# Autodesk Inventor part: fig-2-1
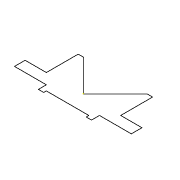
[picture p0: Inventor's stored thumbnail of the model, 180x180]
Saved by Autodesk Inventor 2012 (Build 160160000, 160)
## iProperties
Created: 2011-06
Part Number: fig-2-1
Material: Default
Document SubType Name: Modeling
Designer: CadCim
Density: 1 g/cm^3
Author: CadCim
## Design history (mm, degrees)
sketch "Sketch1"
  geometry: L1 (0, 0)-(-3, 3); L2 (-2, -1.5)-(2, -1.5); L3 (3, 3)-(0, 0); L4 (3.5, 3)-(3, 3); L5 (3.5, 0)-(3.5, 3); L6 (2, -1.75)-(2.5, -1.75); L7 (2.5, -1.75)-(2.5, -1); L8 (5.5, 0)-(3.5, 0); L9 (5.5, -1)-(5.5, 0); L10 (2.5, -1)-(5.5, -1); L11 (2, -1.5)-(2, -1.75); L12 (-3, 3)-(-3.5, 3); L13 (-2, -1.75)-(-2, -1.5); L14 (-2.5, -1.75)-(-2, -1.75); L15 (-2.5, -1)-(-2.5, -1.75); L16 (-5.5, -1)-(-2.5, -1); L17 (-5.5, 0)-(-5.5, -1); L18 (-3.5, 0)-(-5.5, 0); L19 (-3.5, 3)-(-3.5, 0); 1 further point
  constraints: 38 end point, 17 perpendicular, 1 horizontal
